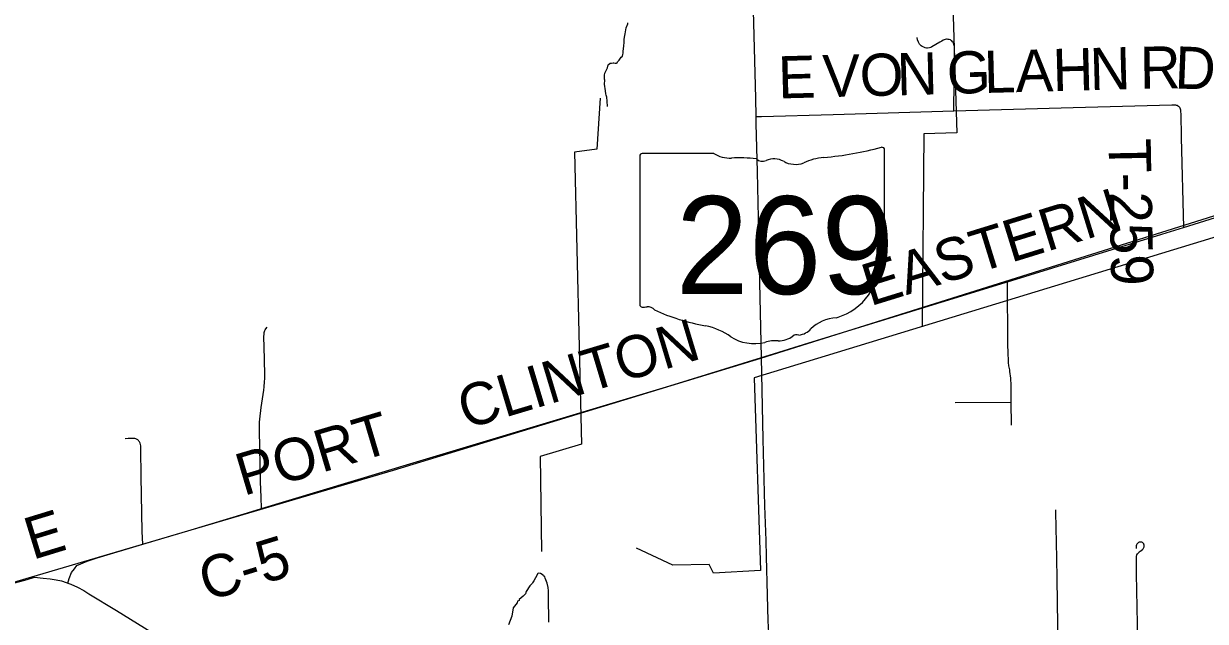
# Model space of a CAD drawing. Extents: x 63.4 to 97.4, y 0.4 to 22.4.
# Drawn here: x 68.112 to 69.704, y 16.043 to 16.848 of the extents above; entities that cross this region are included whole.
import ezdxf

# ---------------------------------------------------------------- set-up
doc = ezdxf.new("R2010")
doc.units = 0
for name, color, linetype in [('GM_X_County_Road', 7, 'Continuous'), ('GM_X_County_Road_Text', 7, 'Continuous'), ('GM_X_Minor_River', 7, 'Continuous'), ('GM_X_Rail_Line', 7, 'Continuous'), ('GM_X_State_Location', 7, 'Continuous'), ('GM_X_State_Route', 7, 'Continuous'), ('GM_X_State_Shield', 7, 'Continuous'), ('GM_X_Township_Road', 7, 'Continuous'), ('GM_X_Township_Road_Text', 7, 'Continuous')]:
    doc.layers.add(name, color=color, linetype=linetype)

msp = doc.modelspace()

# ---------------------------------------------------------------- linework, layer by layer
at = {"layer": 'GM_X_County_Road'}
msp.add_line((68.1836, 16.1181), (68.1976, 16.1241), dxfattribs=at)
for points in [[(69.6745, 16.5737), (69.7908, 16.61), (69.8382, 16.625), (69.9981, 16.6766), (70.1107, 16.7126), (70.2145, 16.7455), (70.2235, 16.748), (70.2316, 16.7501)], [(69.4372, 16.5002), (69.6453, 16.5646), (69.6745, 16.5737)], [(69.1062, 16.3982), (69.1162, 16.4013), (69.1757, 16.4198), (69.4343, 16.4993), (69.4372, 16.5002)], [(68.4325, 16.1949), (68.6369, 16.2563), (68.9825, 16.3601), (69.1062, 16.3982)], [(68.2726, 16.1466), (68.3331, 16.1647), (68.4135, 16.1892), (68.4325, 16.1949)], [(68.1976, 16.1241), (68.2109, 16.1282), (68.2726, 16.1466)], [(68.1712, 16.0944), (68.1734, 16.1006), (68.1765, 16.1087), (68.1802, 16.1137), (68.1836, 16.1181)], [(67.9724, 16.0591), (67.9774, 16.0599), (67.9835, 16.0611), (67.9961, 16.064), (68.0088, 16.0675), (68.0336, 16.0744), (68.09, 16.0918), (68.1165, 16.0994), (68.1264, 16.1022)], [(68.1264, 16.1022), (68.1384, 16.1012), (68.1476, 16.1001), (68.1555, 16.0988), (68.1627, 16.0972), (68.1692, 16.0952), (68.1712, 16.0944), (68.1755, 16.0927), (68.1843, 16.0888), (68.193, 16.0844)], [(68.193, 16.0844), (68.1999, 16.0801), (68.2371, 16.0576), (68.522, 15.8807), (68.6433, 15.8053), (68.7013, 15.7691)]]:
    msp.add_lwpolyline(points, dxfattribs=at)
at = {"layer": 'GM_X_Minor_River'}
for points in [[(69.3587, 17.0295), (69.3691, 16.7012), (69.3247, 16.6998), (69.3226, 16.4402)], [(68.8987, 16.7363), (68.8981, 16.7439), (68.8978, 16.7493), (68.8967, 16.7519), (68.8963, 16.7535), (68.896, 16.7576), (68.8946, 16.7664), (68.8947, 16.7721), (68.8943, 16.7732), (68.8944, 16.7789), (68.8948, 16.7816), (68.8968, 16.785), (68.8987, 16.7887), (68.8995, 16.7925), (68.9022, 16.7951), (68.9037, 16.7951), (68.906, 16.7955), (68.9072, 16.7955), (68.9087, 16.7951), (68.9106, 16.795), (68.9117, 16.7954), (68.9121, 16.7969), (68.914, 16.7988), (68.9171, 16.8029), (68.9187, 16.8044), (68.9191, 16.8067), (68.9195, 16.8082), (68.9195, 16.8109), (68.9204, 16.8177), (68.9208, 16.823), (68.9209, 16.826), (68.9213, 16.831), (68.9217, 16.8317), (68.9217, 16.8321), (68.9221, 16.8344), (68.9238, 16.8423), (68.9258, 16.848), (68.9258, 16.8491)], [(68.8886, 16.7479), (68.884, 16.6791), (68.8541, 16.6748), (68.8637, 16.2815), (68.8079, 16.2648), (68.8097, 16.1371)], [(70.0656, 16.6668), (69.0959, 16.3711), (69.1045, 16.1112), (69.0411, 16.1078), (69.0357, 16.1196), (68.9864, 16.1186), (68.9377, 16.1412)], [(68.8195, 16.0417), (68.8193, 16.0527), (68.8191, 16.0653), (68.8192, 16.0751), (68.819, 16.0839), (68.8186, 16.0884), (68.8172, 16.0941), (68.8147, 16.101), (68.8139, 16.1029), (68.8121, 16.1041), (68.8117, 16.1052), (68.8083, 16.1072), (68.8057, 16.1076), (68.8045, 16.1072), (68.8014, 16.1016), (68.7991, 16.0974), (68.7975, 16.0948), (68.7971, 16.0937), (68.794, 16.0907), (68.789, 16.0828), (68.7882, 16.0797), (68.7847, 16.0768), (68.7797, 16.0723), (68.7793, 16.0711), (68.7774, 16.07), (68.7766, 16.0678), (68.7712, 16.061), (68.7695, 16.05), (68.7652, 16.0379)]]:
    msp.add_lwpolyline(points, dxfattribs=at)
at = {"layer": 'GM_X_Rail_Line'}
msp.add_lwpolyline([(65.5072, 16.0914), (66.1191, 16.083), (66.4239, 16.0787), (66.8313, 16.0688), (67.543, 16.0626), (67.9702, 16.0577), (68.6101, 16.2463), (69.1053, 16.3972), (70.1929, 16.7393), (70.2646, 16.7591), (70.3642, 16.7634), (70.5898, 16.7764), (70.6857, 16.8302), (70.7827, 16.8988), (71.2174, 17.2501), (71.5086, 17.4876), (71.6576, 17.6039), (72.13, 17.975), (72.3072, 18.116)], dxfattribs=at)
at = {"layer": 'GM_X_State_Route'}
for points in [[(69.1062, 16.3982), (69.103, 16.5399), (69.102, 16.5865), (69.1005, 16.6486), (69.099, 16.7138), (69.0988, 16.723), (69.0982, 16.7479), (69.0921, 16.9838), (69.0912, 17.0149), (69.0903, 17.0538), (69.0882, 17.1422), (69.0859, 17.2197), (69.0844, 17.269), (69.0831, 17.3251), (69.0819, 17.3936), (69.0793, 17.4801), (69.0772, 17.5768), (69.0766, 17.6171), (69.0762, 17.6366), (69.0762, 17.6663)], [(69.1142, 16.0782), (69.1128, 16.1302), (69.1124, 16.1519), (69.1105, 16.1984), (69.1082, 16.2884), (69.1062, 16.3982)], [(69.1193, 15.9649), (69.1191, 15.9761), (69.1188, 15.993), (69.1183, 16.0018), (69.118, 16.0074), (69.1176, 16.0108), (69.1172, 16.0144), (69.1159, 16.0273), (69.1151, 16.0433), (69.1142, 16.0782)]]:
    msp.add_lwpolyline(points, dxfattribs=at)
at = {"layer": 'GM_X_State_Shield'}
for p, q in [((68.942, 16.6698), (68.942, 16.4697)), ((69.0418, 16.6733), (68.9453, 16.6733)), ((69.2716, 16.5736), (69.2716, 16.6782)), ((69.2716, 16.5736), (69.2716, 16.5736))]:
    msp.add_line(p, q, dxfattribs=at)
for centre, major_axis, start_param, end_param in [((68.9458, 16.6703), (0.00382, 0), 1.712693, 3.28349), ((69.0648, 16.6965), (0.037, 0), 4.042523, 4.731795), ((69.1542, 16.9461), (0.3495, 0), 4.814394, 5.042369), ((69.268, 16.6787), (0.00367, 0), 6.141152, 7.989035), ((69.0771, 16.5609), (0.133, 0), 1.404758, 1.657858), ((69.1073, 16.6713), (0.0107, 0), 3.836095, 5.185415), ((69.1229, 16.6482), (0.0222, 0), 0.950623, 2.079405), ((69.1516, 16.6799), (0.0267, 0), 4.081561, 5.145723), ((69.1988, 16.6122), (0.0703, 0), 1.699011, 2.107814), ((69.2708, 16.5659), (0.00568, 0), 1.883978, 3.671073), ((69.2347, 16.5526), (0.0341, 0), 5.934695, 6.695948), ((69.2677, 16.5732), (0.00393, 0), 5.05454, 6.418171), ((69.2848, 16.5298), (0.0248, 0), 2.387724, 3.262537), ((69.1738, 16.5164), (0.0874, 0), 5.101752, 6.440018), ((68.9459, 16.4693), (0.00385, 0), 3.00124, 4.508301), ((68.9464, 16.4898), (0.0294, 0), 4.665946, 4.897461), ((68.9525, 16.4582), (0.0106, 0), 0.519207, 1.627899), ((69.0863, 16.638), (0.2524, 0), 4.195997, 4.488961), ((69.2107, 16.4135), (0.0479, 0), 1.647645, 2.488434), ((69.011, 16.3798), (0.079, 0), 0.823519, 1.323587), ((69.15, 16.4503), (0.0282, 0), 4.937069, 5.64225), ((69.0964, 16.4572), (0.0501, 0), 4.026481, 4.996735), ((69.1254, 16.388), (0.0412, 0), 1.495662, 1.94098), ((69.1291, 16.4422), (0.0267, 0), 4.691044, 5.507374), ((69.1532, 16.4228), (0.00752, 0), 1.147584, 2.315152)]:
    msp.add_ellipse(centre, major_axis=major_axis, ratio=0.8, start_param=start_param, end_param=end_param, dxfattribs=at)
at = {"layer": 'GM_X_Township_Road'}
for p in [(69.367, 16.3377), (69.443, 16.3071)]:
    msp.add_line(p, (69.4425, 16.3381), dxfattribs=at)
for points in [[(69.3653, 16.7305), (69.3658, 16.8093), (69.3658, 16.814), (69.3658, 16.8169), (69.3656, 16.8187), (69.3652, 16.8202), (69.3646, 16.8218), (69.364, 16.823), (69.3635, 16.8237), (69.3624, 16.8248), (69.3616, 16.8254), (69.3604, 16.8262), (69.359, 16.8268), (69.3577, 16.827), (69.3563, 16.8271), (69.3552, 16.8271), (69.3536, 16.8268), (69.3523, 16.8263), (69.3507, 16.8257), (69.3488, 16.8247), (69.3461, 16.8232), (69.3354, 16.8168), (69.334, 16.8161), (69.3325, 16.8157), (69.3295, 16.8153), (69.3282, 16.8153), (69.3264, 16.8156), (69.3245, 16.8163), (69.3225, 16.8173), (69.321, 16.8184), (69.3197, 16.8197), (69.3189, 16.8207), (69.3174, 16.8234), (69.3163, 16.8263), (69.3158, 16.8294)], [(69.3653, 16.7305), (69.5259, 16.7351), (69.659, 16.7389), (69.6604, 16.7388), (69.6616, 16.7387), (69.663, 16.7387), (69.6639, 16.7386), (69.6647, 16.7384), (69.6658, 16.7381), (69.6666, 16.7377), (69.6678, 16.7369), (69.6684, 16.7365)], [(69.6684, 16.7365), (69.6691, 16.7357), (69.6698, 16.7345), (69.6701, 16.7339), (69.6702, 16.7333), (69.6705, 16.7322), (69.6706, 16.7312), (69.6707, 16.7302), (69.6707, 16.729), (69.6708, 16.7269), (69.6712, 16.6947), (69.6745, 16.5737)], [(69.0988, 16.723), (69.106, 16.7232), (69.2024, 16.7259), (69.3653, 16.7305)], [(69.4425, 16.3381), (69.4424, 16.3493), (69.4423, 16.3606), (69.4417, 16.3706), (69.4415, 16.3737), (69.4412, 16.3765), (69.4407, 16.3795), (69.4404, 16.3816), (69.4394, 16.3872), (69.4389, 16.3918), (69.4386, 16.3965), (69.4383, 16.4017), (69.4382, 16.4054), (69.438, 16.4148), (69.4372, 16.5002)], [(68.4325, 16.1949), (68.4318, 16.21), (68.4312, 16.2306), (68.4295, 16.2998), (68.4296, 16.3057), (68.4298, 16.3111), (68.4301, 16.3154), (68.4318, 16.3309), (68.4353, 16.3542), (68.4359, 16.3587), (68.4365, 16.3656), (68.4368, 16.3701), (68.4369, 16.3742), (68.4366, 16.396), (68.4357, 16.4272), (68.4358, 16.4295), (68.4358, 16.431), (68.436, 16.4322), (68.4362, 16.4334), (68.4367, 16.4347), (68.4373, 16.4358), (68.438, 16.437), (68.4399, 16.4394)], [(68.2726, 16.1466), (68.2717, 16.1637), (68.27, 16.238), (68.2697, 16.2749), (68.2697, 16.2772), (68.2696, 16.2794), (68.2693, 16.2813), (68.2689, 16.2831), (68.2684, 16.284), (68.2679, 16.2849), (68.2673, 16.2857), (68.2665, 16.2866), (68.2657, 16.2873), (68.2648, 16.2879), (68.264, 16.2884), (68.2631, 16.2887), (68.2616, 16.2891), (68.2608, 16.2892), (68.2596, 16.2893), (68.2577, 16.2894), (68.2556, 16.2894), (68.2527, 16.2892), (68.2487, 16.2889)], [(69.5103, 15.796), (69.5093, 15.8276), (69.5074, 15.9329), (69.5053, 16.0382), (69.5042, 16.1002), (69.5037, 16.128), (69.5026, 16.19), (69.5026, 16.1931)], [(69.615, 15.927), (69.6112, 16.1068), (69.6112, 16.1267), (69.6112, 16.1289), (69.6113, 16.13), (69.6114, 16.131), (69.6115, 16.1318), (69.6118, 16.1325), (69.6125, 16.1336), (69.6133, 16.1346), (69.6137, 16.1351), (69.6144, 16.1357), (69.615, 16.1364), (69.616, 16.1372), (69.617, 16.138), (69.6197, 16.1402), (69.6203, 16.1408), (69.6207, 16.1413), (69.6213, 16.1425), (69.6214, 16.1431), (69.6215, 16.1439), (69.6215, 16.145), (69.6214, 16.1459), (69.6212, 16.1465), (69.6209, 16.1471), (69.6205, 16.1478), (69.6198, 16.1485), (69.6192, 16.1489), (69.6183, 16.1495), (69.6175, 16.1497), (69.6169, 16.1497), (69.6154, 16.1496), (69.6147, 16.1494), (69.6137, 16.1489), (69.6128, 16.1483), (69.612, 16.1474), (69.6115, 16.1466), (69.6113, 16.146), (69.6109, 16.1445), (69.6107, 16.1439), (69.6107, 16.143), (69.6106, 16.1421), (69.6107, 16.1411)]]:
    msp.add_lwpolyline(points, dxfattribs=at)

# ---------------------------------------------------------------- texts
at = {"layer": 'GM_X_County_Road_Text'}
for s, height, rotation, p in [('EASTERN', 0.05682, 17.1812, (69.2524, 16.4672)), ('CLINTON', 0.05682, 16.7127, (68.7074, 16.3014)), ('PORT', 0.05682, 16.5738, (68.4082, 16.2116)), ('E', 0.0568, 17.0212, (68.1239, 16.1254)), ('C-5', 0.05682, 17.1251, (68.3589, 16.0695))]:
    msp.add_text(s, height=height, rotation=rotation, dxfattribs=at).set_placement(p)
at = {"layer": 'GM_X_State_Location'}
msp.add_text('269', height=0.000189, rotation=0, dxfattribs=at).set_placement((69.0363, 16.5427))
for s in ['s', 'r']:
    msp.add_text(s, height=0.000189, dxfattribs=at).set_placement((69.1031, 16.5565))
at = {"layer": 'GM_X_State_Shield'}
msp.add_text('269', height=0.13184, dxfattribs=at).set_placement((68.9905, 16.4838))
at = {"layer": 'GM_X_Township_Road_Text'}
for s, height, rotation, p in [('A', 0.0568, 1.5316, (69.4489, 16.7558)), ('H', 0.0568, 1.5306, (69.4989, 16.7572)), ('N', 0.0568, 1.5362, (69.5489, 16.7585)), ('R', 0.0568, 0.8002, (69.6161, 16.7603)), ('D', 0.0568, 357.6972, (69.662, 16.761)), ('E', 0.0568, 1.5345, (69.129, 16.7473)), ('V', 0.0568, 1.5316, (69.189, 16.7489)), ('O', 0.0568, 1.5316, (69.239, 16.7502)), ('N', 0.0568, 1.5316, (69.289, 16.7515)), ('G', 0.0568, 1.5316, (69.3564, 16.7534)), ('L', 0.0568, 1.5326, (69.4064, 16.7547)), ('T-259', 0.05682, 271.1227, (69.5735, 16.693))]:
    msp.add_text(s, height=height, rotation=rotation, dxfattribs=at).set_placement(p)

doc.saveas('drawing.dxf')
